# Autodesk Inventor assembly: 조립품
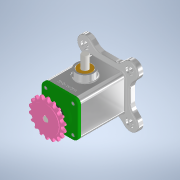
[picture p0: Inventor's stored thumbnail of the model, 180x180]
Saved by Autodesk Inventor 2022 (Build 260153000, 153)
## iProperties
Created: 2022-05
Part Number: 조립품
Document SubType Name: Assembly
Designer: Admin
Author: Admin
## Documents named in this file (11)
- C:\Users\Admin\Desktop\720509V1001\조립품.iam
- C:\Users\Admin\Desktop\720509V1001\본체.ipt
- C:\Users\Admin\Desktop\720509V1001\커버.ipt
- C:\Users\Admin\Desktop\720509V1001\베어링 6203.ipt
- C:\Users\Admin\Desktop\720509V1001\편심축.ipt
- C:\Users\Admin\Desktop\720509V1001\오일 실.ipt
- C:\Users\Admin\Desktop\720509V1001\부시.ipt
- C:\Users\Admin\Desktop\720509V1001\슬라이더.ipt
- C:\Users\Admin\Desktop\720509V1001\키 4 x 4 x 14.ipt
- C:\Users\Admin\Desktop\720509V1001\스프로킷.ipt
- C:\Users\Admin\Desktop\720509V1001\볼트 M4.ipt
